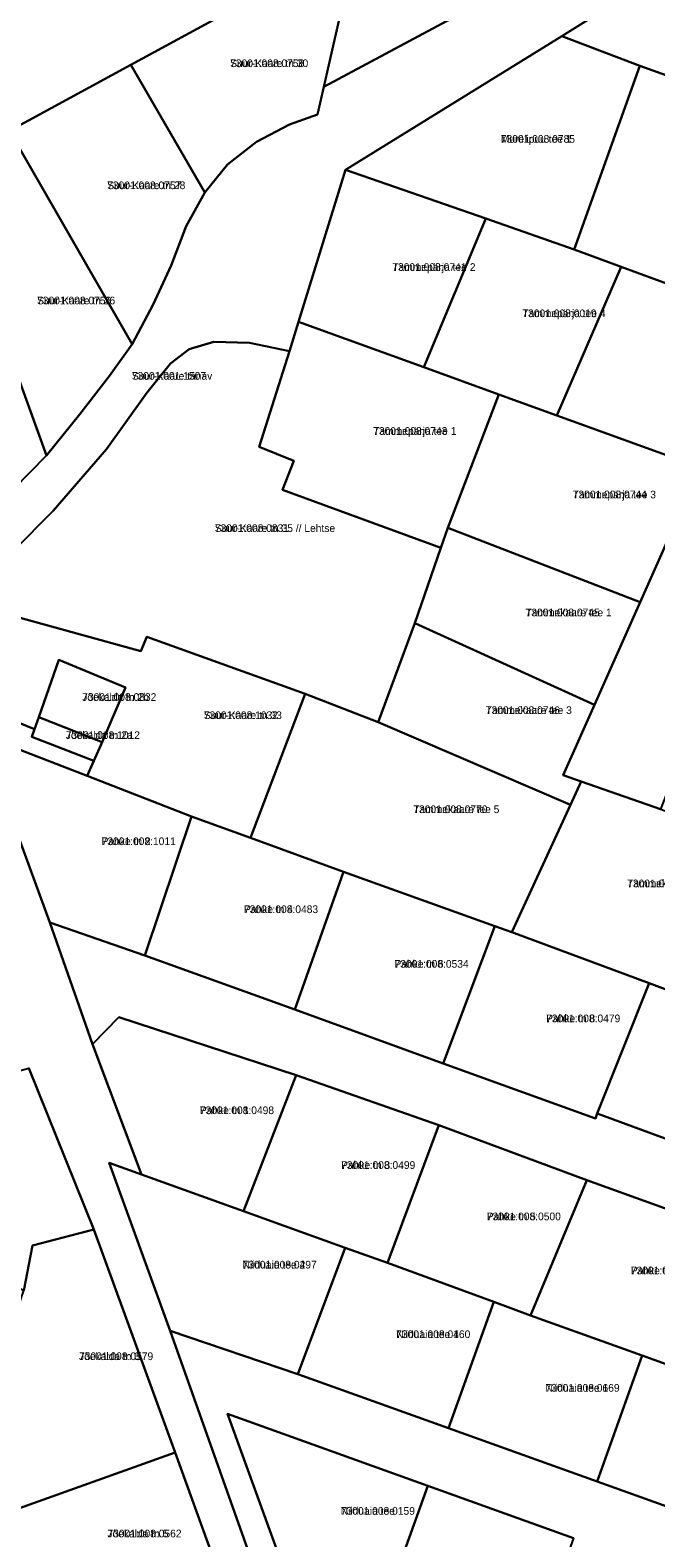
# Model space of a CAD drawing. Extents: x 524000 to 564260, y 6469338 to 6496391.
# Drawn here: x 535276.7 to 535399.1, y 6471359.9 to 6471654.6 of the extents above; entities that cross this region are included whole.
import ezdxf

# ---------------------------------------------------------------- set-up
doc = ezdxf.new("R2010")
doc.units = 0
for name, color, linetype in [('L_AADRESS', 7, 'Continuous'), ('PIIR', 7, 'Continuous'), ('TUNNUS', 7, 'Continuous')]:
    doc.layers.add(name, color=color, linetype=linetype)

msp = doc.modelspace()

# ---------------------------------------------------------------- linework, layer by layer
at = {"layer": 'PIIR'}
for points in [[(535547.13, 6471790.52), (535527.35, 6471771.63), (535509.9, 6471756.13), (535486.55, 6471735.35), (535465.7, 6471718.2), (535453.69, 6471738.52), (535419.25, 6471718.18), (535432.3, 6471696.1), (535334.13, 6471643.54), (535340.59, 6471671.9), (535353.8, 6471729.6), (535367.62, 6471737.37), (535427.17, 6471768.76), (535446.07, 6471783.63), (535469.52, 6471805.29), (535470.71, 6471806.96), (535513.7, 6471798.28), (535536.44, 6471794.16)], [(535259.48, 6471627.78), (535217.58, 6471604.98), (535209.46, 6471626.15), (535192.49, 6471672.19), (535181.92, 6471700.4), (535193.16, 6471708.66), (535222.98, 6471730.03), (535245.26, 6471746), (535256.63, 6471754.15), (535278.58, 6471723.1), (535295.83, 6471698.83), (535322.02, 6471712.75), (535351.12, 6471728.21), (535353.8, 6471729.6), (535340.58, 6471671.89), (535296.36, 6471647.85), (535272.65, 6471634.95)], [(535296.36, 6471647.85), (535340.58, 6471671.89), (535332.86, 6471638.14), (535327.39, 6471636.17), (535320.95, 6471632.75), (535315.31, 6471628.32), (535310.87, 6471622.87)], [(535380.64, 6471653.45), (535385.87, 6471656.69), (535407.58, 6471668.53), (535442.96, 6471654.66), (535434.86, 6471633.66), (535421.72, 6471638.36), (535395.91, 6471647.63)], [(535338.39, 6471627.29), (535380.64, 6471653.45), (535395.91, 6471647.63), (535383.06, 6471611.74), (535365.81, 6471617.75)], [(535296.36, 6471647.85), (535310.87, 6471622.87), (535307.19, 6471616.28), (535304.24, 6471608.59), (535300.76, 6471600.99), (535296.62, 6471593.23), (535272.65, 6471634.95)], [(535383.06, 6471611.74), (535395.91, 6471647.63), (535421.72, 6471638.36), (535408.26, 6471602.44), (535392.25, 6471608.35)], [(535269.23, 6471600.81), (535259.48, 6471627.78), (535272.65, 6471634.95), (535296.62, 6471593.23), (535292.21, 6471587), (535286.43, 6471579.53), (535279.87, 6471571.42)], [(535338.39, 6471627.29), (535365.81, 6471617.75), (535353.66, 6471588.73), (535329.2, 6471597.59)], [(535353.66, 6471588.73), (535365.81, 6471617.75), (535383.06, 6471611.74), (535392.25, 6471608.35), (535379.72, 6471579.28), (535368.36, 6471583.4)], [(535392.25, 6471608.35), (535408.26, 6471602.44), (535418.44, 6471598.59), (535406.34, 6471569.64), (535379.72, 6471579.28)], [(535247.59, 6471543.86), (535233.51, 6471581.46), (535269.23, 6471600.81), (535279.87, 6471571.42), (535273.45, 6471564.87), (535267.84, 6471559.35), (535261.82, 6471554.07), (535250.12, 6471545.39)], [(535328.25, 6471570.42), (535321.48, 6471573.12), (535327.4, 6471591.87), (535329.2, 6471597.59), (535353.66, 6471588.73), (535368.36, 6471583.4), (535358.36, 6471557.3), (535357.02, 6471553.4), (535326.05, 6471564.76)], [(535298.35, 6471533.23), (535262.16, 6471543.16), (535273.35, 6471552.77), (535281.18, 6471560.63), (535291.62, 6471572.7), (535299.49, 6471583.72), (535304.11, 6471589.41), (535307.78, 6471592.22), (535312.59, 6471593.7), (535319.59, 6471593.5), (535327.4, 6471591.87), (535321.48, 6471573.12), (535328.25, 6471570.42), (535326.05, 6471564.76), (535357.02, 6471553.4), (535351.94, 6471538.67), (535344.74, 6471519.31), (535330.48, 6471524.85), (535299.52, 6471536.03)], [(535368.36, 6471583.4), (535379.72, 6471579.28), (535406.34, 6471569.64), (535407.73, 6471569.15), (535395.99, 6471542.77), (535358.36, 6471557.3)], [(535380.94, 6471508.97), (535387.06, 6471522.71), (535395.99, 6471542.77), (535407.73, 6471569.15), (535423.84, 6471563.31), (535399.98, 6471502.3), (535384.47, 6471507.73)], [(535357.02, 6471553.4), (535358.36, 6471557.3), (535395.99, 6471542.77), (535387.06, 6471522.71), (535351.94, 6471538.67)], [(535299.52, 6471536.03), (535330.48, 6471524.85), (535319.77, 6471496.7), (535308.25, 6471500.88), (535287.82, 6471508.81), (535289.14, 6471511.78), (535290.75, 6471515.42), (535295.37, 6471526.1), (535282.29, 6471531.53), (535278.4, 6471520.3), (535277.54, 6471517.95), (535268.87, 6471521.49), (535273.31, 6471534.04), (535260.23, 6471537.66), (535262.16, 6471543.16), (535298.35, 6471533.23)], [(535351.94, 6471538.67), (535387.06, 6471522.71), (535380.94, 6471508.97), (535384.47, 6471507.73), (535382.37, 6471503.17), (535344.74, 6471519.31)], [(535290.75, 6471515.42), (535278.4, 6471520.3), (535282.29, 6471531.53), (535295.37, 6471526.1)], [(535319.77, 6471496.7), (535330.48, 6471524.85), (535344.74, 6471519.31), (535382.37, 6471503.17), (535370.86, 6471478.25), (535367.6, 6471479.46), (535337.98, 6471490.08)], [(535277.54, 6471517.95), (535278.4, 6471520.3), (535290.75, 6471515.42), (535289.14, 6471511.78), (535277, 6471516.48)], [(535267.04, 6471516.85), (535287.82, 6471508.81), (535308.25, 6471500.88), (535299.1, 6471473.73), (535280.53, 6471480.15)], [(535382.37, 6471503.17), (535384.47, 6471507.73), (535399.98, 6471502.3), (535414.97, 6471496.99), (535416.12, 6471496.57), (535402.97, 6471466.37), (535397.72, 6471468.32), (535370.86, 6471478.25)], [(535308.25, 6471500.88), (535319.77, 6471496.7), (535337.98, 6471490.08), (535328.47, 6471463.12), (535299.1, 6471473.73)], [(535337.98, 6471490.08), (535367.6, 6471479.46), (535357.49, 6471452.57), (535328.47, 6471463.12)], [(535367.6, 6471479.46), (535370.86, 6471478.25), (535397.72, 6471468.32), (535387.55, 6471442.79), (535387.27, 6471441.85), (535357.49, 6471452.57)], [(535397.72, 6471468.32), (535402.97, 6471466.37), (535426.34, 6471457.64), (535416.68, 6471432.16), (535387.55, 6471442.79)], [(535288.89, 6471456.39), (535294.01, 6471461.68), (535328.71, 6471450.34), (535318.41, 6471423.71), (535298.46, 6471430.88)], [(535244.19, 6471444.7), (535247.1, 6471451.56), (535249.57, 6471452.9), (535262.34, 6471447.86), (535276.41, 6471451.68), (535289.15, 6471420.16), (535277.12, 6471416.99), (535275.43, 6471408.19), (535235.72, 6471424.53)], [(535318.41, 6471423.71), (535328.71, 6471450.34), (535356.61, 6471440.54), (535346.57, 6471413.63), (535338.33, 6471416.56)], [(535356.61, 6471440.54), (535385.56, 6471429.81), (535374.56, 6471403.35), (535367.38, 6471405.99), (535346.57, 6471413.63)], [(535292.12, 6471433.16), (535298.46, 6471430.88), (535318.41, 6471423.71), (535338.33, 6471416.56), (535329.03, 6471391.87), (535304.08, 6471400.35)], [(535385.56, 6471429.81), (535413.56, 6471419.69), (535403.45, 6471392.96), (535396.41, 6471395.49), (535374.56, 6471403.35)], [(535267.48, 6471376.94), (535267.5, 6471376.95), (535268.93, 6471389.6), (535275.43, 6471408.19), (535277.12, 6471416.99), (535289.15, 6471420.16), (535305.02, 6471376.56), (535271.18, 6471364.46)], [(535338.33, 6471416.56), (535346.57, 6471413.63), (535367.38, 6471405.99), (535358.51, 6471381.29), (535329.03, 6471391.87)], [(535367.38, 6471405.99), (535374.56, 6471403.35), (535396.41, 6471395.49), (535387.56, 6471370.87), (535358.51, 6471381.29)], [(535396.41, 6471395.49), (535403.45, 6471392.96), (535425.41, 6471384.87), (535416.63, 6471360.43), (535387.56, 6471370.87)], [(535315.3, 6471384.12), (535354.45, 6471370.05), (535345.32, 6471344.64), (535327.3, 6471351.1)], [(535271.18, 6471364.46), (535305.02, 6471376.56), (535312.55, 6471355.86), (535277.55, 6471343.35)], [(535345.32, 6471344.64), (535354.45, 6471370.05), (535382.97, 6471359.8), (535373.85, 6471334.44), (535363.75, 6471338.03)]]:
    msp.add_lwpolyline(points, close=True, dxfattribs=at)
for points in [[(535273.45, 6471564.87), (535279.87, 6471571.42), (535286.43, 6471579.53), (535292.21, 6471587), (535296.62, 6471593.23), (535300.76, 6471600.99), (535304.24, 6471608.59), (535307.19, 6471616.28), (535310.87, 6471622.87), (535315.31, 6471628.32), (535320.95, 6471632.75), (535327.39, 6471636.17), (535332.86, 6471638.14), (535334.13, 6471643.54), (535432.3, 6471696.1)], [(535385.87, 6471656.69), (535380.64, 6471653.45), (535338.39, 6471627.29), (535329.2, 6471597.59), (535327.4, 6471591.87), (535319.59, 6471593.5), (535312.59, 6471593.7), (535307.78, 6471592.22), (535304.11, 6471589.41), (535299.49, 6471583.72), (535291.62, 6471572.7), (535281.18, 6471560.63), (535273.35, 6471552.77)], [(535268.87, 6471521.49), (535277.54, 6471517.95), (535277, 6471516.48), (535289.14, 6471511.78), (535287.82, 6471508.81), (535267.04, 6471516.85), (535280.53, 6471480.15), (535288.89, 6471456.39), (535298.46, 6471430.88), (535292.12, 6471433.16), (535304.08, 6471400.35), (535321.36, 6471351.63), (535332.73, 6471316.67), (535345, 6471274.89), (535348.92, 6471273.62), (535383.44, 6471178.14), (535419.87, 6471078.92)], [(535413.56, 6471419.69), (535385.56, 6471429.81), (535356.61, 6471440.54), (535328.71, 6471450.34), (535294.01, 6471461.68), (535288.89, 6471456.39), (535280.53, 6471480.15), (535299.1, 6471473.73), (535328.47, 6471463.12), (535357.49, 6471452.57), (535387.27, 6471441.85), (535387.55, 6471442.79), (535416.68, 6471432.16)], [(535379.36, 6471168.36), (535371.46, 6471189.89), (535364.17, 6471209.73), (535356.5, 6471230.63), (535348.75, 6471251.73), (535341.21, 6471272.28), (535333.63, 6471292.92), (535326.13, 6471313.33), (535327.82, 6471313.92), (535320.29, 6471334.61), (535312.55, 6471355.86), (535305.02, 6471376.56), (535289.15, 6471420.16), (535276.41, 6471451.68)], [(535321.36, 6471351.63), (535304.08, 6471400.35), (535329.03, 6471391.87), (535358.51, 6471381.29), (535387.56, 6471370.87), (535416.63, 6471360.43), (535445.69, 6471350)], [(535382.97, 6471359.8), (535354.45, 6471370.05), (535315.3, 6471384.12), (535327.3, 6471351.1)]]:
    msp.add_lwpolyline(points, dxfattribs=at)

# ---------------------------------------------------------------- texts
at = {"layer": 'L_AADRESS'}
for s, p in [('Suur-Kaare tn 30', (535315.8, 6471647.38)), ('Murelipuu tee 1', (535368.74, 6471632.59)), ('Suur-Kaare tn 28', (535291.76, 6471623.52)), ('Tammepärja tee 2', (535347.51, 6471607.54)), ('Suur-Kaare tn 26', (535278.05, 6471601)), ('Tammepärja tee 4', (535372.95, 6471598.5)), ('Suur-Kaare tänav', (535296.59, 6471586.26)), ('Tammepärja tee 1', (535343.78, 6471575.49)), ('Tammepärja tee 3', (535382.8, 6471563.08)), ('Suur-Kaare tn 35 // Lehtse', (535312.81, 6471556.5)), ('Tammekaare tee 1', (535373.58, 6471540.01)), ('Jõekalda tn 2b', (535286.87, 6471523.48)), ('Suur-Kaare tn 33', (535310.65, 6471519.93)), ('Tammekaare tee 3', (535365.8, 6471520.92)), ('Jõekalda tn 2a', (535283.66, 6471516.04)), ('Tammekaare tee 5', (535351.62, 6471501.55)), ('Pahke tn 2', (535290.67, 6471495.29)), ('Tammekaare tee 7', (535393.45, 6471487.05)), ('Pahke tn 4', (535318.51, 6471482)), ('Pahke tn 6', (535347.95, 6471471.32)), ('Pahke tn 8', (535377.6, 6471460.66)), ('Pahke tn 1', (535309.89, 6471442.7)), ('Pahke tn 3', (535337.51, 6471431.99)), ('Pahke tn 5', (535365.98, 6471421.95)), ('Niiduaia tee 2', (535318.23, 6471412.52)), ('Pahke tn 7', (535394.16, 6471411.38)), ('Niiduaia tee 4', (535348.27, 6471398.92)), ('Jõekalda tn 3', (535286.25, 6471394.62)), ('Niiduaia tee 6', (535377.47, 6471388.43)), ('Niiduaia tee 1', (535337.44, 6471364.38)), ('Jõekalda tn 5', (535291.8, 6471359.96))]:
    msp.add_text(s, height=1.5, dxfattribs=at).set_placement(p)
at = {"layer": 'TUNNUS'}
for s, p in [('73001:008:0758', (535315.8, 6471647.38)), ('73001:008:0785', (535368.74, 6471632.59)), ('73001:008:0757', (535291.76, 6471623.52)), ('73001:008:0741', (535347.51, 6471607.54)), ('73001:008:0756', (535278.05, 6471601)), ('73001:008:0019', (535372.95, 6471598.5)), ('73001:001:1507', (535296.59, 6471586.26)), ('73001:008:0743', (535343.78, 6471575.49)), ('73001:008:0744', (535382.8, 6471563.08)), ('73001:008:0831', (535312.81, 6471556.5)), ('73001:008:0745', (535373.58, 6471540.01)), ('73001:008:0832', (535286.87, 6471523.48)), ('73001:008:1032', (535310.65, 6471519.93)), ('73001:008:0746', (535365.8, 6471520.92)), ('73001:008:1012', (535283.66, 6471516.04)), ('73001:008:0770', (535351.62, 6471501.55)), ('73001:008:1011', (535290.67, 6471495.29)), ('73001:008:0817', (535393.45, 6471487.05)), ('73001:008:0483', (535318.51, 6471482)), ('73001:008:0534', (535347.95, 6471471.32)), ('73001:008:0479', (535377.6, 6471460.66)), ('73001:008:0498', (535309.89, 6471442.7)), ('73001:008:0499', (535337.51, 6471431.99)), ('73001:008:0500', (535365.98, 6471421.95)), ('73001:008:0497', (535318.23, 6471412.52)), ('73001:008:0478', (535394.16, 6471411.38)), ('73001:008:0160', (535348.27, 6471398.92)), ('73001:008:0579', (535286.25, 6471394.62)), ('73001:008:0169', (535377.47, 6471388.43)), ('73001:008:0159', (535337.44, 6471364.38)), ('73001:008:0562', (535291.8, 6471359.96))]:
    msp.add_text(s, height=1.5, dxfattribs=at).set_placement(p)

doc.saveas('drawing.dxf')
